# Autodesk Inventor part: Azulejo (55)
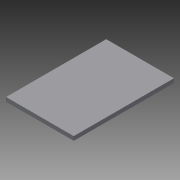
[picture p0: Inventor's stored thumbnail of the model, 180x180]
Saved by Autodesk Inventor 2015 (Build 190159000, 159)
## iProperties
Created: 2015-04
Part Number: Azulejo (55)
Material: Genérico
Document SubType Name: Modeling
Designer: Felipe
Density: 1 g/cm^3
Appearance: Padrão
Author: Felipe
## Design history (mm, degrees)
sketch "Sketch1"
  geometry: L1 (320.115, 1877.424)-(320.115, 397.424); L2 (720.115, 397.424)-(720.115, 1877.424); L3 (720.115, 1877.424)-(320.115, 1877.424); L4 (320.115, 397.424)-(720.115, 397.424); L5 (1800.115, 397.424)-(800.115, 397.424); L6 (800.115, 397.424)-(800.115, 1877.424); L7 (800.115, 1877.424)-(1800.115, 1877.424); L8 (1800.115, 1877.424)-(1800.115, 397.424); 1 further point
  constraints: 16 end point
extrude "Extrusion1" new body sketch "Sketch1" distance "d0" = 60; taper "d1" = 0 deg
body "Solid1"
